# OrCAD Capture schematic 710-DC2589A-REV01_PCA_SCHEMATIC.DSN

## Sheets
1 PAGE1: size C; note: 100MHz Isolated DAC SPI Serial Interface Demo Circuit
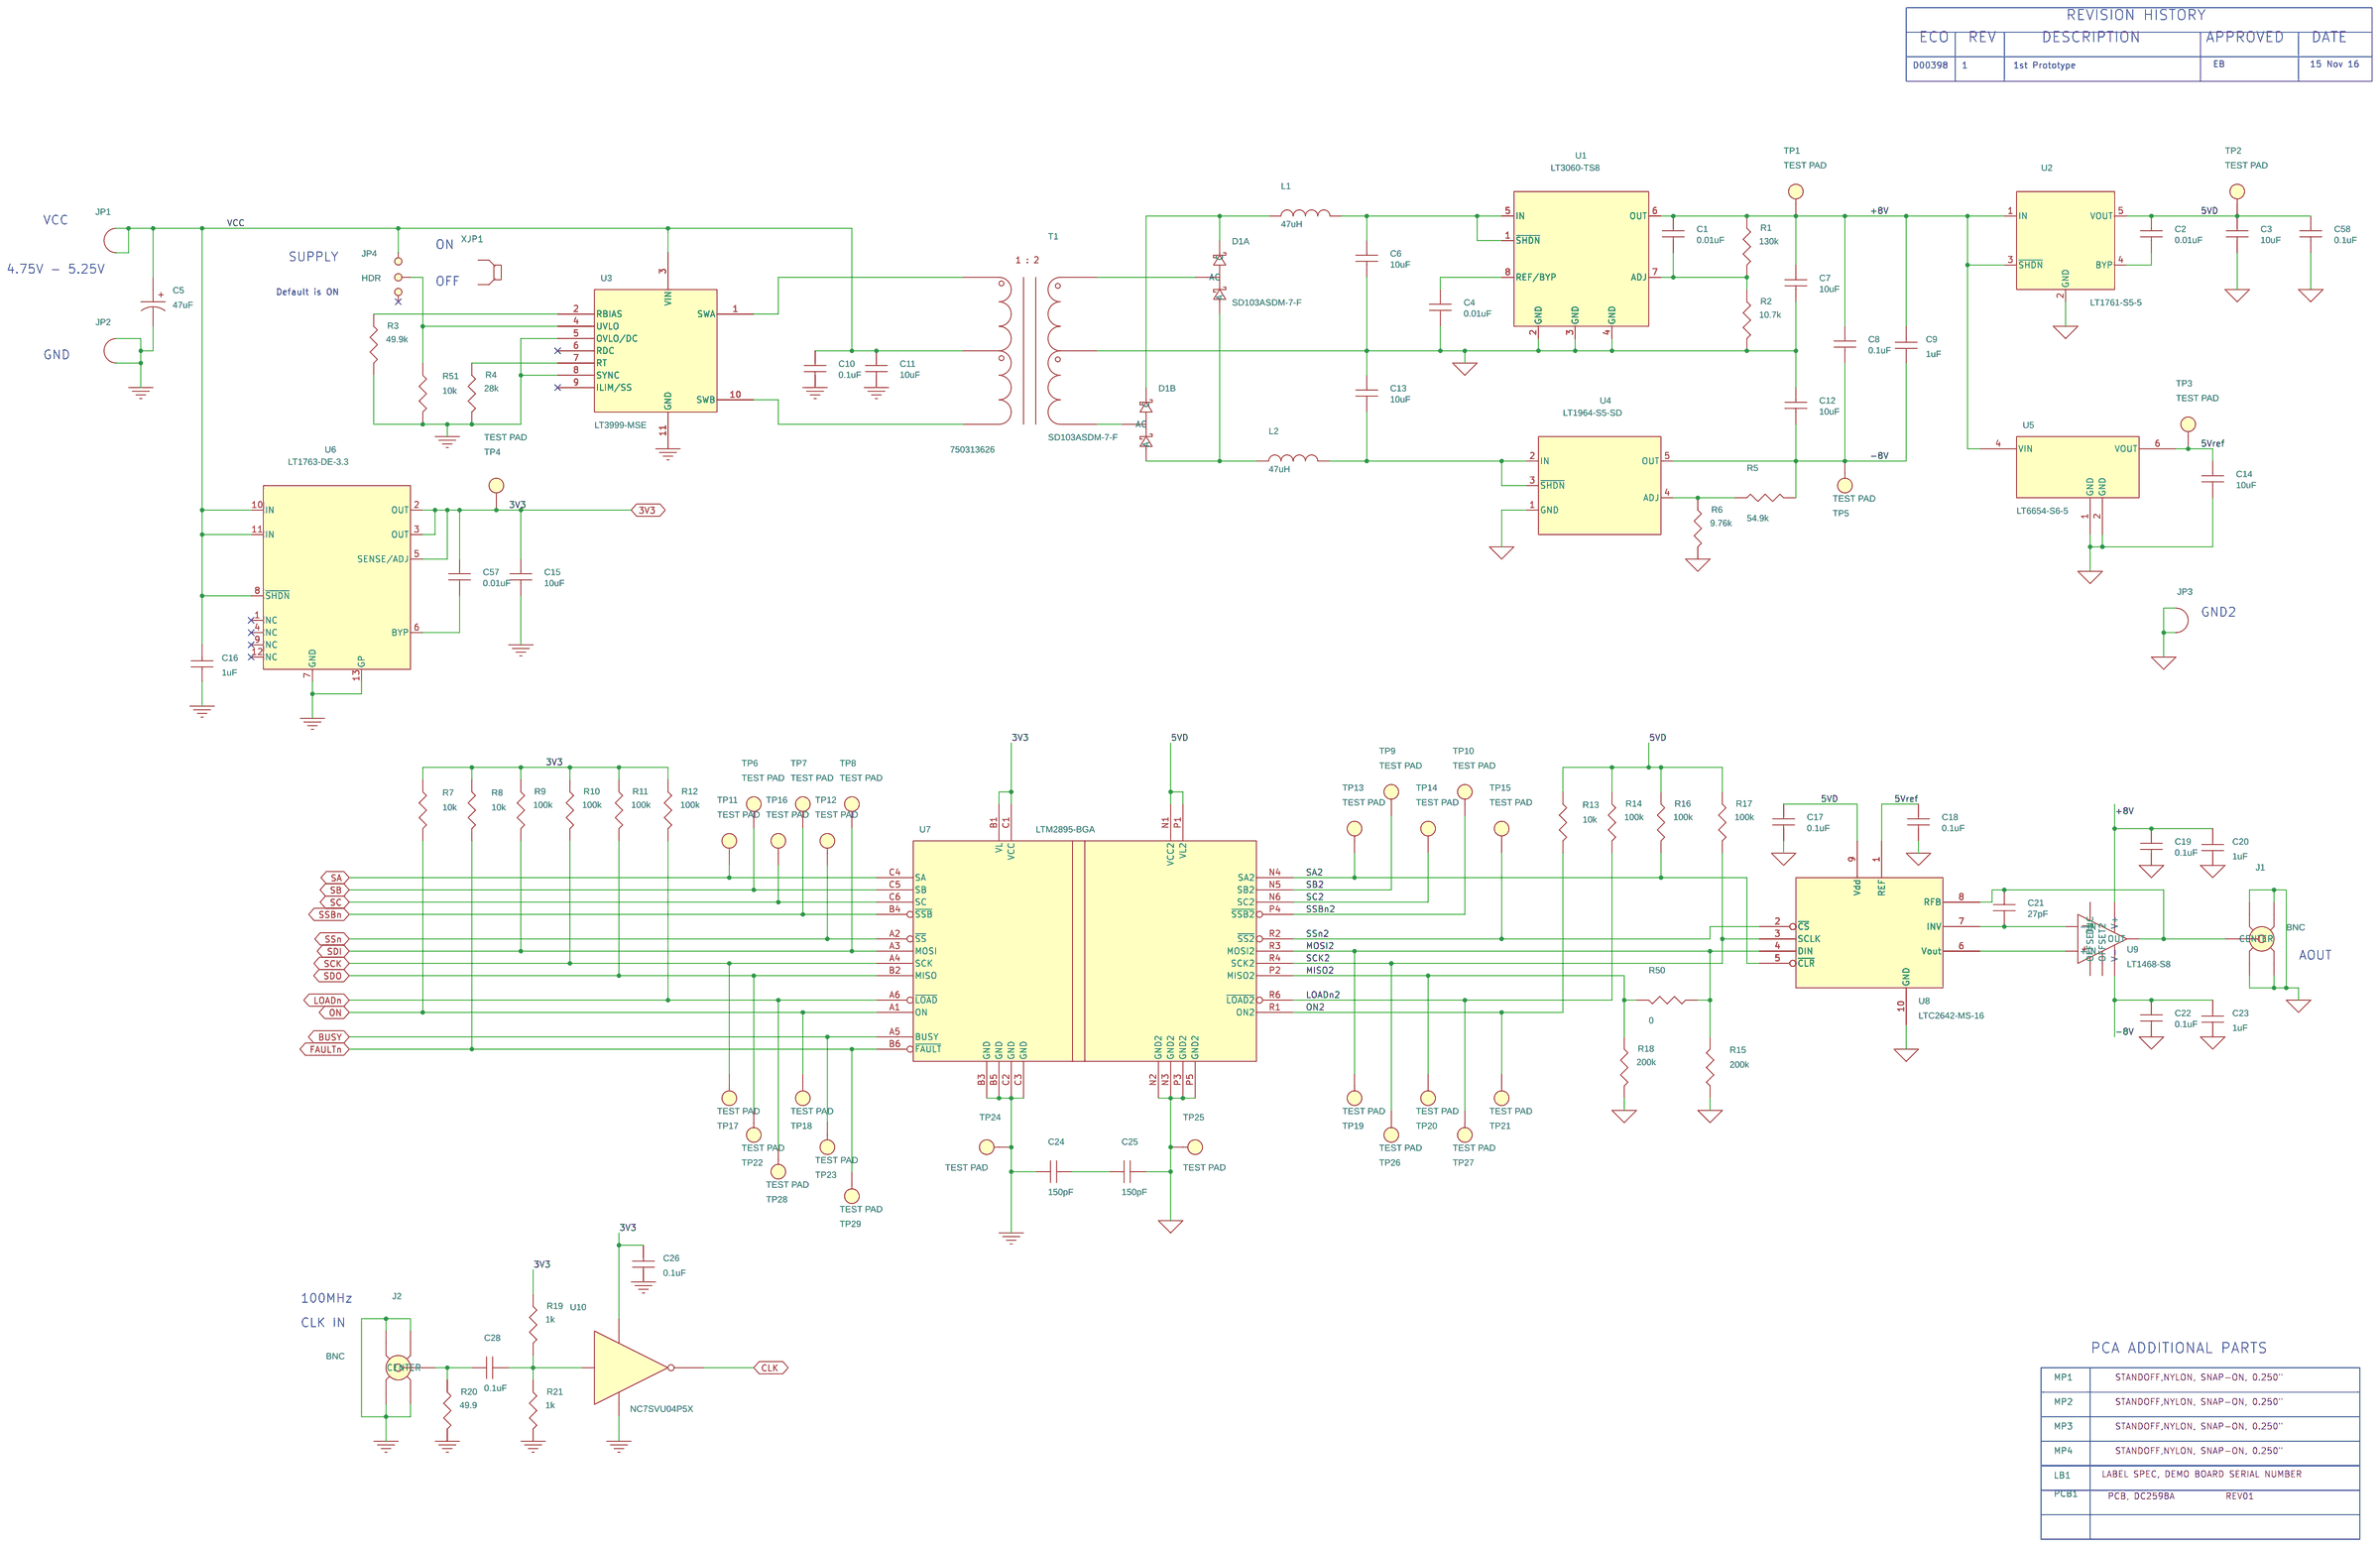
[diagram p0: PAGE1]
2 PAGE2: size C
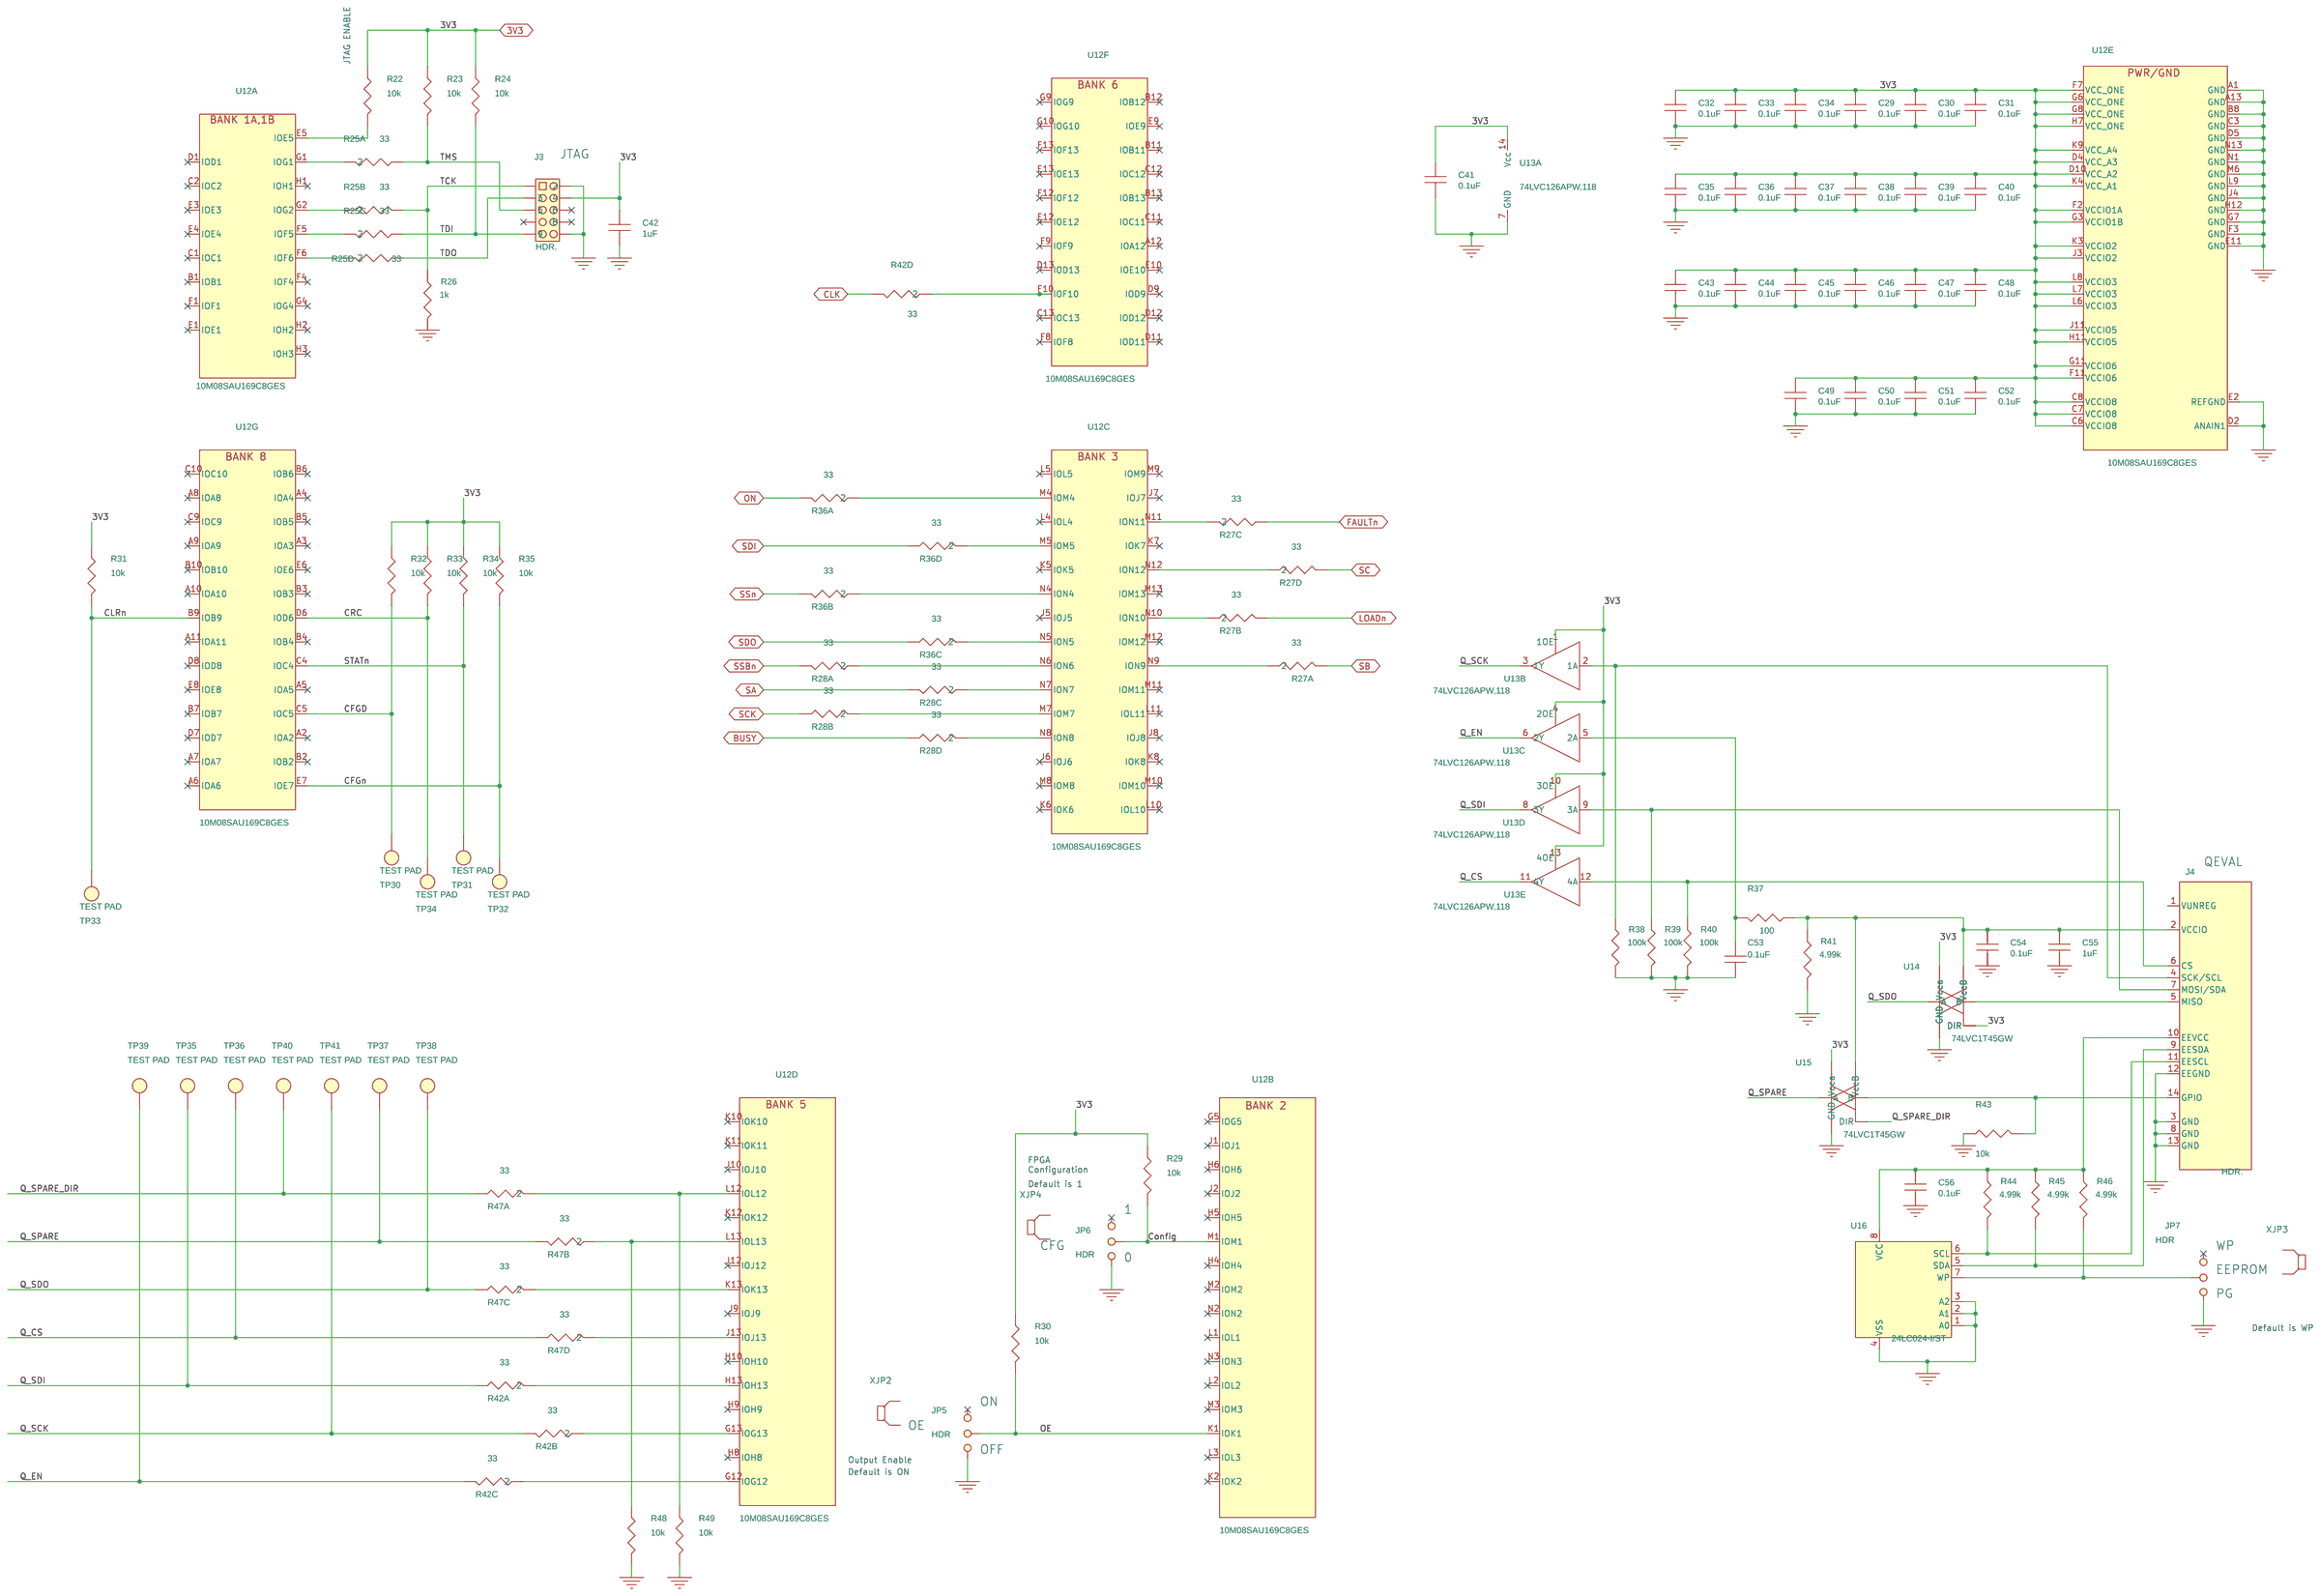
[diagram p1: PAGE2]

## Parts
sheet PAGE1
C1  0.01uF  [CC0402N]
C2  0.01uF  [CC0402N]
C3  10uF  [CC1210N]
C4  0.01uF  [CC0402N]
C5  47uF  [CAPMP6032N]
C6  10uF  [CC1210N]
C7  10uF  [CC1210N]
C8  0.1uF  [CC0402N]
C9  1uF  [CC0603N]
C10  0.1uF  [CC0402N]
C11  10uF  [CC1210N]
C12  10uF  [CC1210N]
C13  10uF  [CC1210N]
C14  10uF  [CC1210N]
C15  10uF  [CC1210N]
C16  1uF  [CC0603N]
C17  0.1uF  [CC0402N]
C18  0.1uF  [CC0402N]
C19  0.1uF  [CC0402N]
C20  1uF  [CC0603N]
C21  27pF  [CC0402N]
C22  0.1uF  [CC0402N]
C23  1uF  [CC0603N]
C24  150pF  [CC1808N]
C25  150pF  [CC1808N]
C26  0.1uF  [CC0402N]
C28  0.1uF  [CC0402N]
C57  0.01uF  [CC0402N]
C58  0.1uF  [CC0402N]
D1  SD103ASDM-7-F  [DIODES-SOT26-6]  (sections A,B)
J1  BNC  [AMPHENOL-112640]
J2  BNC  [AMPHENOL-112640]
JP1  HEAT SINK PASSIVE BGA ANCHOR  [AAVID_125700D00000G]
JP2  HEAT SINK PASSIVE BGA ANCHOR  [AAVID_125700D00000G]
JP3  HEAT SINK PASSIVE BGA ANCHOR  [AAVID_125700D00000G]
JP4  HDR  [HD1X3-079]
L1  47uH  [COILCRAFT-XFL3012]
L2  47uH  [COILCRAFT-XFL3012]
LB1  LABEL  [895-0154_REV01]
MP1  STANDOFF  [MTG-8831]
MP2  STANDOFF  [MTG-8831]
MP3  STANDOFF  [MTG-8831]
MP4  STANDOFF  [MTG-8831]
PCB1  PCB, DC2598A
R1  130k  [CR0402N]
R2  10.7k  [CR0603N]
R3  49.9k  [CR0603N]
R4  28k  [CR0603N]
R5  54.9k  [CR0603N]
R6  9.76k  [CR0402N]
R7  10k  [CR0402N]
R8  10k  [CR0402N]
R9  100k  [CR0603N]
R10  100k  [CR0603N]
R11  100k  [CR0603N]
R12  100k  [CR0603N]
R13  10k  [CR0402N]
R14  100k  [CR0603N]
R15  200k  [CR0603N]
R16  100k  [CR0603N]
R17  100k  [CR0603N]
R18  200k  [CR0603N]
R19  1k  [CR0603N]
R20  49.9  [CR1206N]
R21  1k  [CR0603N]
R50  0  [CR0805N]
R51  10k  [CR0402N]
T1  750313626  [WURTH-PKG-0948]
TP1  TEST PAD  [PADSTYLE1]
TP2  TEST PAD  [PADSTYLE1]
TP3  TEST PAD  [PADSTYLE1]
TP4  TEST PAD  [PADSTYLE1]
TP5  TEST PAD  [PADSTYLE1]
TP6  TEST PAD  [PADSTYLE1]
TP7  TEST PAD  [PADSTYLE1]
TP8  TEST PAD  [PADSTYLE1]
TP9  TEST PAD  [PADSTYLE1]
TP10  TEST PAD  [PADSTYLE1]
TP11  TEST PAD  [PADSTYLE1]
TP12  TEST PAD  [PADSTYLE1]
TP13  TEST PAD  [PADSTYLE1]
TP14  TEST PAD  [PADSTYLE1]
TP15  TEST PAD  [PADSTYLE1]
TP16  TEST PAD  [PADSTYLE1]
TP17  TEST PAD  [PADSTYLE1]
TP18  TEST PAD  [PADSTYLE1]
TP19  TEST PAD  [PADSTYLE1]
TP20  TEST PAD  [PADSTYLE1]
TP21  TEST PAD  [PADSTYLE1]
TP22  TEST PAD  [PADSTYLE1]
TP23  TEST PAD  [PADSTYLE1]
TP24  TEST PAD  [PADSTYLE1]
TP25  TEST PAD  [PADSTYLE1]
TP26  TEST PAD  [PADSTYLE1]
TP27  TEST PAD  [PADSTYLE1]
TP28  TEST PAD  [PADSTYLE1]
TP29  TEST PAD  [PADSTYLE1]
U1  LT3060-TS8  [LTC-TS8-8-1637]
U2  LT1761-S5-5  [LTC-S5-5-1635]
U3  LT3999-MSE  [LTC-MSE-10-1664]
U4  LT1964-S5-SD  [LTC-S5-5-1635]
U5  LT6654-S6-5  [LTC-S6-6-1636]
U6  LT1763-DE-3.3  [LTC-DE/UE-12-1695]
U7  LTM2895-BGA  [LTC-BGA-36-1987]
U8  LTC2642-MS-16  [LTC-MS-10-1661]
U9  LT1468-S8  [LTC-S8-8-1610(S8)]
U10  NC7SVU04P5X  [SC70-5]
XJP1  SHUNT
sheet PAGE2
C29  0.1uF  [CC0402N]
C30  0.1uF  [CC0402N]
C31  0.1uF  [CC0402N]
C32  0.1uF  [CC0402N]
C33  0.1uF  [CC0402N]
C34  0.1uF  [CC0402N]
C35  0.1uF  [CC0402N]
C36  0.1uF  [CC0402N]
C37  0.1uF  [CC0402N]
C38  0.1uF  [CC0402N]
C39  0.1uF  [CC0402N]
C40  0.1uF  [CC0402N]
C41  0.1uF  [CC0402N]
C42  1uF  [CC0805N]
C43  0.1uF  [CC0402N]
C44  0.1uF  [CC0402N]
C45  0.1uF  [CC0402N]
C46  0.1uF  [CC0402N]
C47  0.1uF  [CC0402N]
C48  0.1uF  [CC0402N]
C49  0.1uF  [CC0402N]
C50  0.1uF  [CC0402N]
C51  0.1uF  [CC0402N]
C52  0.1uF  [CC0402N]
C53  0.1uF  [CC0402N]
C54  0.1uF  [CC0402N]
C55  1uF  [CC0805N]
C56  0.1uF  [CC0402N]
J3  HDR.  [SAMTEC_TSW-105-07-L-D]
J4  HDR.  [HD2X7-079-MOLEX]
JP5  HDR  [HD1X3-079]
JP6  HDR  [HD1X3-079]
JP7  HDR  [HD1X3-079]
R22  10k  [CR0402N]
R23  10k  [CR0402N]
R24  10k  [CR0402N]
R25  33  [PANASONIC-EXB38V]  (sections A,B,C,D)
R26  1k  [CR0603N]
R27  33  [PANASONIC-EXB38V]  (sections A,B,C,D)
R28  33  [PANASONIC-EXB38V]  (sections A,B,C,D)
R29  10k  [CR0402N]
R30  10k  [CR0402N]
R31  10k  [CR0402N]
R32  10k  [CR0402N]
R33  10k  [CR0402N]
R34  10k  [CR0402N]
R35  10k  [CR0402N]
R36  33  [PANASONIC-EXB38V]  (sections A,B,C,D)
R37  100  [CR0603N]
R38  100k  [CR0603N]
R39  100k  [CR0603N]
R40  100k  [CR0603N]
R41  4.99k  [CR0603N]
R42  33  [PANASONIC-EXB38V]  (sections A,B,C,D)
R43  10k  [CR0402N]
R44  4.99k  [CR0603N]
R45  4.99k  [CR0603N]
R46  4.99k  [CR0603N]
R47  33  [PANASONIC-EXB38V]  (sections A,B,C,D)
R48  10k  [CR0402N]
R49  10k  [CR0402N]
TP30  TEST PAD  [PADSTYLE1]
TP31  TEST PAD  [PADSTYLE1]
TP32  TEST PAD  [PADSTYLE1]
TP33  TEST PAD  [PADSTYLE1]
TP34  TEST PAD  [PADSTYLE1]
TP35  TEST PAD  [PADSTYLE1]
TP36  TEST PAD  [PADSTYLE1]
TP37  TEST PAD  [PADSTYLE1]
TP38  TEST PAD  [PADSTYLE1]
TP39  TEST PAD  [PADSTYLE1]
TP40  TEST PAD  [PADSTYLE1]
TP41  TEST PAD  [PADSTYLE1]
U12  10M08SAU169C8GES  [ALTERA-169UBGA]  (sections A,B,C,D,E,F,G)
U13  74LVC126APW,118  [TSSOP-14N]  (sections A,B,C,D,E)
U14  74LVC1T45GW  [NXP-SOT363]
U15  74LVC1T45GW  [NXP-SOT363]
U16  24LC024-I/ST  [MICROCHIP-TSSOP-8]
XJP2  SHUNT
XJP3  SHUNT
XJP4  SHUNT

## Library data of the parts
C1 C2 C4 C57 = CAP: CAP.,0.01uF,X7R,50V,10%,0402; CLASS: DISCRETE; Dielectric Type: X7R; FPLIST: CC0402N,CC0402L,CC0402M; Manufacturer: KEMET; Manufacturer PN: C0402C103K5RAC7867; PART_NUMBER: 150-0041; Package Size: 0402; Rated Voltage: 50V; Tolerance: 10%
C3 C6 C7 C11-C15 = CAP: CAP.,10uF,X7R,35V,10%,1210; CLASS: DISCRETE; Dielectric Type: X7R; FPLIST: CC1210N,CC1210L,CC1210M; Manufacturer: MURATA; Manufacturer PN: GRM32ER7YA106KA12L; PART_NUMBER: 150-0365; Package Size: 1210; Rated Voltage: 35V; Tolerance: 10%
C5 = CAP_P: CAP.,47uF,16V,10%,2413; CLASS: DISCRETE; FPLIST: CAPMP6032N,CAPMP6032L,CAPMP6032M; Manufacturer: Kemet; Manufacturer PN: T494C476K016AT; PART_NUMBER: 150-0521; Package Size: 2413; Package Type: Surface Mount; Rated Voltage: 16V; Tolerance: 10%
C8 C10 C17-C19 C22 C26 C28-C41 C43-C54 C56 C58 = CAP: CAP.,0.1uF,X7R,50V,10%,0402; CLASS: DISCRETE; Dielectric Type: X7R; FPLIST: CC0402N,CC0402L,CC0402M; Manufacturer: MURATA; Manufacturer PN: GRM155R71H104KE14D; PART_NUMBER: 150-3240; Package Size: 0402; Package Type: SMD; Rated Voltage: 50V; Tolerance: 10%
C9 C16 C20 C23 = CAP: CAP.,1uF,X7R,35V,10%,0603; CLASS: DISCRETE; Dielectric Type: X7R; FPLIST: CC0603N,CC0603L,CC0603M; Manufacturer: TDK; Manufacturer PN: C1608X7R1V105K080AC; PART_NUMBER: 150-0522; Package Size: 0603; Package Type: Surface Mount, MLCC; Rated Voltage: 35V; Temperature Coefficient: X7R; Tolerance: 10%
C21 = CAP: CAP.,27pF,C0G,50V,5%,0402; CLASS: DISCRETE; Dielectric Type: C0G; FPLIST: CC0402N,CC0402L,CC0402M; Manufacturer: MURATA; Manufacturer PN: GRM1555C1H270JZ01D; PART_NUMBER: 150-0093; Package Size: 0402; Rated Voltage: 50V; Tolerance: 5%
C24 C25 = CAP: CAP CER 150PF 250VAC X7R 1808; CLASS: DISCRETE; Dielectric Type: X7R; FPLIST: CC1808N,CC1808L,CC1808M; Manufacturer: MURATA; Manufacturer PN: GA342QR7GF151KW01L; PART_NUMBER: 150-0523; Package Size: 1808; Package Type: Surface Mount, MLCC; Rated Voltage: 250VAC; Temperature Coefficient: X7R; Tolerance: 10%
D1 = DIODES-SD103ASDM: DIODE,SCHOTTKY,40V,225mW,SOT-26; CLASS: DISCRETE; Manufacturer: DIODES,INC; PART_NUMBER: 210-0233; Package Size: SOT-26-6; Rated Voltage: 40V
J1 J2 = BNC_50_OHM_112404: CONN.,BNC,FEMALE,16.97mm X 11.02mm,EDGE MT; CLASS: IO; Manufacturer: AMPHENOL; Manufacturer PN: 112640; Operating Temperature Minimum: -55C - 85C; PART_NUMBER: 250-0631
JP1-JP3 = test_probe_jumper: Heat Sink Passive BGA Anchor; CLASS: DISCRETE; Manufacturer: Aavid Thermalloy; Manufacturer PN: 125700D00000G; PART_NUMBER: 930-0004
JP4-JP7 = 3_PIN_HEADER_.079_SINGLE_ROW: CONN.,HDR,MALE,1x3,2mm,THT, STR; CLASS: IO; Manufacturer: Wurth Elektronik; Manufacturer PN: 62000311121; PART_NUMBER: 250-0484
L1 L2 = IND: IND.,47uH,POWER SHIELDED,20%,460mA,1212; CLASS: DISCRETE; Manufacturer: Coilcraft; Manufacturer PN: XFL3012-473MEB; PART_NUMBER: 200-0446; Package Size: 1212; Tolerance: 20%
LB1 = BLANK_LABEL: LABEL SPEC, DEMO BOARD SERIAL NUMBER; Manufacturer: BRADY; Manufacturer PN: THT-96-717-10; PART_NUMBER: 895-0154
MP1-MP4 = BLANK_MECHANICAL_PART: STANDOFF,NYLON, SNAP-ON, 0.250"; CLASS: MECHANICAL PART; Manufacturer: KEYSTONE; Manufacturer PN: 8831; PART_NUMBER: 763-0006
PCB1 = BLANK_PCB_PART: BOM Notes: REV01; CLASS: DISCRETE; Manufacturer: EAGLE ELECTRONICS, INC; Manufacturer PN: 600-DC2598A; PART_NUMBER: 600-DC2598A
R1 = RES: RES.,130k OHMS,1%,1/16W,0402; CLASS: DISCRETE; FPLIST: CR0402N,CR0402L,CR0402M; Manufacturer: NIC; Manufacturer PN: NRC04F1303TRF; PART_NUMBER: 100-2547; Package Size: 0402; Rated Power: 1/16W; Temperature Coefficient: 100ppm/C; Tolerance: 1%
R2 = RES: RES.,10.7k OHMS,1%,1/10W,0603; CLASS: DISCRETE; FPLIST: CR0603N,CR0603L,CR0603M; Manufacturer: NIC; Manufacturer PN: NRC06F1072TRF; PART_NUMBER: 100-2719; Package Size: 0603; Rated Power: 1/10W; Temperature Coefficient: 100ppm/C; Tolerance: 1%
R3 = RES: RES.,49.9k OHMS,1%,1/10W,0603; CLASS: DISCRETE; FPLIST: CR0603N,CR0603L,CR0603M; Manufacturer: VISHAY; Manufacturer PN: CRCW060349K9FKEA; PART_NUMBER: 100-0303; Package Size: 0603; Rated Power: 1/10W; Temperature Coefficient: 100ppm/C; Tolerance: 1%
R4 = RES: RES.,28k OHMS,1%,1/10W,0603; CLASS: DISCRETE; FPLIST: CR0603N,CR0603L,CR0603M; Manufacturer: PANASONIC; Manufacturer PN: ERJ3EKF2802V; PART_NUMBER: 100-0094; Package Size: 0603; Rated Power: 1/10W; Temperature Coefficient: 100ppm/C; Tolerance: 1%
R5 = RES: RES.,54.9k OHMS,1%,1/10W,0603; CLASS: DISCRETE; FPLIST: CR0603N,CR0603L,CR0603M; Manufacturer: VISHAY; Manufacturer PN: CRCW060354K9FKEA; PART_NUMBER: 100-0336; Package Size: 0603; Rated Power: 1/10W; Temperature Coefficient: 100ppm; Tolerance: 1%
R6 = RES: RES.,9.76k OHMS,1%,1/16W,0402; CLASS: DISCRETE; FPLIST: CR0402N,CR0402L,CR0402M; Manufacturer: VISHAY; Manufacturer PN: CRCW04029K76FKED; PART_NUMBER: 100-0488; Package Size: 0402; Rated Power: 1/16W; Temperature Coefficient: 100ppm; Tolerance: 1%
R7 R8 R13 R22-R24 R29-R35 R43 R48 R49 R51 = RES: RES.,10k OHMS,1%,1/16W,0402; CLASS: DISCRETE; FPLIST: CR0402N,CR0402L,CR0402M; Manufacturer: NIC; Manufacturer PN: NRC04F1002TRF; PART_NUMBER: 100-2545; Package Size: 0402; Rated Power: 1/16W; Temperature Coefficient: 100ppm/C; Tolerance: 1%
R9-R12 R14 R16 R17 R38-R40 = RES: RES.,AEC-Q200,100k OHMS,5%,1/10W,0603; CLASS: DISCRETE; FPLIST: CR0603N,CR0603L,CR0603M; Manufacturer: VISHAY; Manufacturer PN: CRCW0603100KJNEA; PART_NUMBER: 100-0312; Package Size: 0603; Rated Power: 1/10W; Temperature Coefficient: 200ppm/C; Tolerance: 5%
R15 R18 = RES: RES.,200k OHMS,1%,1/10W,0603; CLASS: DISCRETE; FPLIST: CR0603N,CR0603L,CR0603M; Manufacturer: VISHAY; Manufacturer PN: CRCW0603200KFKEA; PART_NUMBER: 100-2378; Package Size: 0603; Rated Power: 1/10W; Temperature Coefficient: 100ppm/C; Tolerance: 1%
R19 R21 R26 = RES: RES.,1k OHM,1%,1/10W,0603; CLASS: DISCRETE; FPLIST: CR0603N,CR0603L,CR0603M; Manufacturer: NIC; Manufacturer PN: NRC06F1001TRF; PART_NUMBER: 100-2422; Package Size: 0603; Rated Power: 1/10W; Temperature Coefficient: 100ppm; Tolerance: 1%
R20 = RES: RES.,49.9 OHMS,1%,1/4W,1206; CLASS: DISCRETE; FPLIST: CR1206N,CR1206L,CR1206M; Manufacturer: NIC; Manufacturer PN: NRC12F49R9TRF; PART_NUMBER: 100-2791; Package Size: 1206; Rated Power: 1/4W; Temperature Coefficient: 100ppm/C; Tolerance: 1%
R50 = RES: RES.,0 OHM,1/8W,0805; CLASS: DISCRETE; FPLIST: CR0805N,CR0805L,CR0805M; Manufacturer: VISHAY; Manufacturer PN: CRCW08050000Z0EA; PART_NUMBER: 100-0024; Package Size: 0805; Rated Power: 1/8W
T1 = 750313626: TRANSFORMER,SWITCHING,2:1,9.14mm X 12.7mm; CLASS: DISCRETE; Manufacturer: WURTH ELEKTRONIK; PART_NUMBER: 410-0081; Package Size: 9.14mm L x 8.00mm W; Turns Ratio: 2:1
TP1-TP41 = PAD_STYLE_C: TESTPOINT, PCB COPPER FEATURE; CLASS: IO; FPLIST: PADSTYLE1,PADSTYLE2,PADSTYLE3,PADSTYLE4,PADSTYLE5,PADSTYLE6,PADSTYLE7,PADSTYLE8; Manufacturer: N/A; Manufacturer PN: N/A; PART_NUMBER: PCBPADS-1
U1 = LT3060-TS8-X: IC,LDO LINEAR REGULATOR,TSOT23-8; CLASS: IC; Manufacturer: LINEAR TECHNOLOGY; Manufacturer PN: LT3060ETS8#PBF; PART_NUMBER: LT3060ETS8#PBF; Package Size: SOT-23; Package Type: TSOT23-8
U2 = LT1761-S5-X: IC,LOW NOISE, LDO MICROPOWER REG.,TSOT23-5,100mA, 5V; CLASS: IC; Manufacturer: LINEAR TECHNOLOGY; Manufacturer PN: LT1761ES5-5#PBF; PART_NUMBER: LT1761ES5-5#PBF; Package Size: TSOT-23; Package Type: TSOT23-5
U3 = LT3999-MSE: IC,DC CONTROLLER, PUSH-PULL,10-pin MSOP EP; CLASS: IC; Manufacturer: LINEAR TECHNOLOGY; Manufacturer PN: LT3999IMSE#PBF; PART_NUMBER: LT3999IMSE#PBF; Package Type: 10-pin MSOP EP; Supply Voltage: 36 V
U4 = LT1964-S5-SD: IC,LDO Neg. Micropower Regulator,SOT23-5,200mA, 5V; CLASS: IC; Manufacturer: LINEAR TECHNOLOGY; Manufacturer PN: LT1964ES5-SD#PBF; PART_NUMBER: LT1964ES5-SD#PBF; Package Size: SOT23-5; Package Type: SOT23-5
U5 = LT6654-S6-X: Precision Wide Supply High Output Drive Low Noise Reference, SOT-23; CLASS: IC; Manufacturer: LINEAR TECHNOLOGY; Manufacturer PN: LT6654BHS6-5#TRMPBF; PART_NUMBER: LT6654BHS6-5#TRMPBF; Package Type: 6-pin TSOT-23
U6 = LT1763-DE-X: IC,Low Noise LDO Micropower REG,DFN-12,500mA, 3.3V; CLASS: IC; Manufacturer: LINEAR TECHNOLOGY; Manufacturer PN: LT1763CDE-3.3#PBF; PART_NUMBER: LT1763CDE-3.3#PBF; Package Type: DFN-12
U7 = LTM2895-BGA: IC,100MHz Isolated DAC SPI Serial; CLASS: IC; Manufacturer: LINEAR TECHNOLOGY; Manufacturer PN: LTM2895IY#PBF; PART_NUMBER: LTM2895IY#PBF
U8 = LTC2642-MS-X: IC,16-14-12-Bit VOUT DACs,10-pin MSOP; CLASS: IC; Manufacturer: LINEAR TECHNOLOGY; Manufacturer PN: LTC2642AIMS-16#PBF; PART_NUMBER: LTC2642AIMS-16#PBF; Package Type: 10-pin MSOP
U9 = LT1468-S8_ALT1: IC,70MHz 22us 16Bit Accurate OA,SO-8; CLASS: IC; Manufacturer: LINEAR TECHNOLOGY; Manufacturer PN: LT1468CS8#PBF; PART_NUMBER: LT1468CS8#PBF; Package Size: S8; Package Type: SO-8
U10 = NC7SVU04P5X-SC70-5: IC,ULP-A UNBUFFERED INVERTER,SC70-5; CLASS: IC; Manufacturer: FAIRCHILD SEMI; PART_NUMBER: 280-0491
XJP1-XJP4 = SHUNT_2MM: CONN.,SHUNT,FEMALE,2 POS,2mm; CLASS: IO; Manufacturer: SAMTEC; Manufacturer PN: 2SN-BK-G; PART_NUMBER: 250-0419
C42 C55 = CAP: CAP.,1uF,X7R,10V,10%,0805; CLASS: DISCRETE; Dielectric Type: X7R; FPLIST: CC0805N,CC0805L,CC0805M; Manufacturer: MURATA; Manufacturer PN: GRM21BR71A105KA01L; PART_NUMBER: 150-0153; Package Size: 0805; Rated Voltage: 10V; Tolerance: 10%
J3 = CONN._JTAG_2X5_0.100: CONN.,HDR.,MALE,2x5,2.54mm,THT, STR,MATTE TIN ON TAIL; CLASS: IO; Manufacturer: SAMTEC; Manufacturer PN: TSW-105-07-L-D; PART_NUMBER: 250-0518
J4 = CONN_2X7_.079_MOLEX_RIBBON_A: CONN.,HDR.,MALE,2x7,2mm,THT, VERT,SHROUDED; CLASS: IO; Manufacturer: MOLEX; Manufacturer PN: 87831-1420; PART_NUMBER: 250-0403
R25 R27 R28 R36 R42 R47 = ARRAY_4_RES_SMT_ALT: RES.,ARRAY AEC-Q200,33 OHMS,5%,1/16W,1206; CLASS: DISCRETE; Manufacturer: PANASONIC; Manufacturer PN: EXB-38V330JV; PART_NUMBER: 103-0024; Package Size: 1206; Rated Power: 1/16W; Temperature Coefficient: +/-200PPM; Tolerance: 5%
R37 = RES: RES.,AEC-Q200,100 OHMS,1%,1/10W,0603; CLASS: DISCRETE; Manufacturer: PANASONIC; Manufacturer PN: ERJ3EKF1000V; PART_NUMBER: 100-2769; Package Size: 0603; Rated Power: 1/10W; Temperature Coefficient: 100ppm/C; Tolerance: 1%
R41 R44-R46 = RES: RES.,4.99k OHMS,1%,1/10W,0603; CLASS: DISCRETE; FPLIST: CR0603N,CR0603L,CR0603M; Manufacturer: PANASONIC; Manufacturer PN: ERJ3EKF4991V; PART_NUMBER: 100-0121; Package Size: 0603; Rated Power: 1/10W; Temperature Coefficient: 100ppm/C; Tolerance: 1%
U12 = 10M08SAU169C8GES: IC,FPGA, MAX 10, 8000 CELLS,169 PIN UFBGA; CLASS: IC; Manufacturer: ALTERA; Manufacturer PN: 10M08SAU169C8G; PART_NUMBER: 280-0550; Package Type: 169 PIN UFBGA
U13 = 74LVC126A: IC,BUFF DVR TRI-ST QUAD,14-pin TSSOP; CLASS: IC; FPLIST: TSSOP-14N,TSSOP-14L,TSSOP-14M; Manufacturer: NXP Semiconductors; PART_NUMBER: 280-0599; Package Size: 14-TSSOP (0.173", 4.40mm Width); Package Type: 14-pin TSSOP; Supply Voltage: 1.2 V - 3.6 V
U14 U15 = 74LVC1T45: IC,DUAL SUPPLY TRANSCEIVER,SOT363-6 (SC88),SMD,3-STATE OUTPUTS; CLASS: IC; Manufacturer: NXP SEMICONDUCTORS; Manufacturer PN: 74LVC1T45GW,125; PART_NUMBER: 280-8080; Package Type: SOT363-6 (SC88),SMD
U16 = 24LC024-I_ST_TSSOP-8: IC,EEPROM, I2C,TSSOP-8,2Kb (256 x 8), 400kHz; CLASS: IC; Manufacturer: MICROCHIP; PART_NUMBER: 280-0494; Package Size: TSSOP-8; Package Type: TSSOP-8

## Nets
3V3: C15.1 C26.2 C29.1 C30.1 C31.1 C32.1 C33.1 C34.1 C35.1 C36.1 C37.1 C38.1 C39.1 C40.1 C41.1 C42.1 C43.1 C44.1 C45.1 C46.1 C47.1 C48.1 C49.1 C50.1 C51.1 C52.1 C57.1 J3.4 R7.1 R8.1 R9.1 R10.1 R11.1 R12.1 R19.1 R22.1 R23.1 R24.1 R29.1 R30.1 R31.1 R32.1 R33.1 R34.1 R35.1 TP4.1 U6.2(OUT) U6.3(OUT) U6.5(SENSE/ADJ) U7.B1(VL) U7.C1(VCC) U10.5 U12.C6(VCCIO8) U12.C7(VCCIO8) U12.C8(VCCIO8) U12.D4(VCC_A3) U12.D10(VCC_A2) U12.F2(VCCIO1A) U12.F7(VCC_ONE) U12.F11(VCCIO6) U12.G3(VCCIO1B) U12.G6(VCC_ONE) U12.G8(VCC_ONE) U12.G11(VCCIO6) U12.H7(VCC_ONE) U12.H11(VCCIO5) U12.J3(VCCIO2) U12.J11(VCCIO5) U12.K3(VCCIO2) U12.K4(VCC_A1) U12.K9(VCC_A4) U12.L6(VCCIO3) U12.L7(VCCIO3) U12.L8(VCCIO3) U13.1(1OE) U13.4(2OE) U13.10(3OE) U13.13(4OE) U13.14(Vcc) U14.1(Vcca) U14.5(DIR) U15.1(Vcca)
5VD: C2.1 C3.1 C17.1 C58.1 R13.1 R14.1 R16.1 R17.1 TP2.1 U2.5(VOUT) U7.N1(VCC2) U7.P1(VL2) U8.9(Vdd)
5Vref: C14.1 C18.1 TP3.1 U5.6(VOUT) U8.1(REF)
+8V: C1.1 C7.1 C8.1 C9.2 C19.1 C20.2 R1.1 TP1.1 U1.6(OUT) U2.1(IN) U2.3(~{SHDN}) U5.4(VIN) U9.7(V+)
-8V: C8.2 C9.1 C12.2 C22.1 C23.2 R5.2 TP5.1 U4.5(OUT) U9.4(V-)
GND: C5.2 C10.2 C11.2 C15.2 C16.1 C24.1 C26.1 C29.2 C30.2 C31.2 C32.2 C33.2 C34.2 C35.2 C36.2 C37.2 C38.2 C39.2 C40.2 C41.2 C42.2 C43.2 C44.2 C45.2 C46.2 C47.2 C48.2 C49.2 C50.2 C51.2 C52.2 C53.2 C54.2 C55.2 C56.2 J2.2 J2.3 J2.4 J2.5 J3.2 J3.10 J4.3(GND) J4.8(GND) J4.12(EEGND) J4.13(GND) JP2.1 JP2.2 JP5.1 JP6.1 JP7.1 R3.2 R4.2 R20.2 R21.2 R26.2 R38.2 R39.2 R40.2 R41.2 R43.1 R48.2 R49.2 R51.2 TP24.1 U3.5(OVLO/DC) U3.8(SYNC) U3.11(GND) U6.7(GND) U6.13(GP) U7.B3(GND) U7.B5(GND) U7.C2(GND) U7.C3(GND) U10.3 U12.A1(GND) U12.A13(GND) U12.B8(GND) U12.C3(GND) U12.D2(ANAIN1) U12.D5(GND) U12.E2(REFGND) U12.E11(GND) U12.F3(GND) U12.G7(GND) U12.H12(GND) U12.J4(GND) U12.L9(GND) U12.M6(GND) U12.N1(GND) U12.N13(GND) U13.7(GND) U14.2(GND) U15.2(GND) U16.1(A0) U16.2(A1) U16.3(A2) U16.4(VSS)
GND_SIGNAL: C3.2 C4.2 C6.2 C7.2 C12.1 C13.1 C14.2 C17.2 C18.2 C19.2 C20.1 C22.2 C23.1 C25.2 C58.2 J1.2 J1.3 J1.4 J1.5 JP3.1 JP3.2 R2.2 R6.2 R15.1 R18.2 T1.5 TP25.1 U1.2(GND) U1.3(GND) U1.4(GND) U2.2(GND) U4.1(GND) U5.1(GND) U5.2(GND) U7.N2(GND2) U7.N3(GND2) U7.P3(GND2) U7.P5(GND2) U8.10(GND)
VCC: C5.1 C10.1 C11.1 C16.2 JP1.1 JP1.2 JP4.3 T1.2 U3.3(VIN) U6.8(~{SHDN}) U6.10(IN) U6.11(IN)
BUSY: R28.4 TP23.1 U7.A5(BUSY)
CFGD: R32.2 TP30.1 U12.C5(IOC5)
CFGn: R35.2 TP32.1 U12.E7(IOE7)
CLK: R42.4 U10.4
CLRn: R31.2 TP33.1 U12.B9(IOB9)
Config: JP6.2 R29.2 U12.M1(IOM1)
CRC: R33.2 TP34.1 U12.D6(IOD6)
FAULTn: R8.2 R27.3 TP29.1 U7.B6(~{FAULT})
LOADn: R12.2 R27.2 TP28.1 U7.A6(~{LOAD})
LOADn2: R14.2 TP27.1 U7.R6(~{LOAD2})
MISO2: R18.1 R50.2 TP20.1 U7.P2(MISO2)
MOSI2: R15.2 R50.1 TP19.1 U7.R3(MOSI2) U8.4(DIN)
OE: JP5.2 R30.2 U12.K1(IOK1)
ON: R7.2 R36.1 TP18.1 U7.A1(ON)
ON2: R13.2 TP21.1 U7.R1(ON2)
Q_CS: R47.4 TP36.1 U13.11(4Y)
Q_EN: R42.3 TP39.1 U13.6(2Y)
Q_SCK: R42.2 TP41.1 U13.3(1Y)
Q_SDI: R42.1 TP35.1 U13.8(3Y)
Q_SDO: R47.3 TP38.1 U14.3(A)
Q_SPARE: R47.2 TP37.1 U15.3(A)
Q_SPARE_DIR: R47.1 TP40.1 U15.5(DIR)
SA: R28.3 TP11.1 U7.C4(SA)
SA2: R16.2 TP13.1 U7.N4(SA2) U8.5(~{CLR})
SB: R27.1 TP6.1 U7.C5(SB)
SB2: TP9.1 U7.N5(SB2)
SC: R27.4 TP16.1 U7.C6(SC)
SC2: TP14.1 U7.N6(SC2)
SCK: R10.2 R28.2 TP17.1 U7.A4(SCK)
SCK2: R17.2 TP26.1 U7.R4(SCK2) U8.3(SCLK)
SDI: R9.2 R36.4 TP8.1 U7.A3(MOSI)
SDO: R11.2 R36.3 TP22.1 U7.B2(MISO)
SSBn: R28.1 TP7.1 U7.B4(~{SSB})
SSBn2: TP10.1 U7.P4(~{SSB2})
SSn: R36.2 TP12.1 U7.A2(~{SS})
SSn2: TP15.1 U7.R2(~{SS2}) U8.2(~{CS})
STATn: R34.2 TP31.1 U12.C4(IOC4)
TCK: J3.1 R25.2 R26.1
TDI: J3.9 R24.2 R25.3
TDO: J3.3 R25.4
TMS: J3.5 R23.2 R25.1
N839686: U8.6(Vout) U9.3(+IN)
N839690: C21.2 U8.7(INV) U9.2(-IN)
N839694: C21.1 J1.1(CENTER) U8.8(RFB) U9.6(OUT)
N842809: D1.6(AC) T1.6
N842934: D1.2(C) D1.5(C) L1.1
N842958: D1.1(A) D1.4(A) L2.1
N843358: D1.3(AC) T1.4
N843663: T1.3 U3.10(SWB)
N843678: T1.1 U3.1(SWA)
N844267: C13.2 L2.2 U4.2(IN) U4.3(~{SHDN})
N844386: C6.1 L1.2 U1.1(~{SHDN}) U1.5(IN)
N844896: C4.1 U1.8(REF/BYP)
N844903: C1.2 R1.2 R2.1 U1.7(ADJ)
N848408: C2.2 U2.4(BYP)
N850776: R3.1 U3.2(RBIAS)
N850991: R4.1 U3.7(RT)
N864411: C24.2 C25.1
N864851: C56.1 J4.10(EEVCC) R44.1 R45.1 R46.1 U16.8(VCC)
N865521: J4.11(EESCL) R44.2 U16.6(SCL)
N865527: J4.4(SCK/SCL) R38.1 U13.2(1A)
N865545: J4.9(EESDA) R45.2 U16.5(SDA)
N865574: JP7.2 R46.2 U16.7(WP)
N866616: J4.5(MISO) U14.4(B)
N866898: C54.1 C55.1 J4.2(VCCIO) R37.1 R41.1 U14.6(VccB) U15.6(VccB)
N867394: J4.14(GPIO) R43.2 U15.4(B)
N870820: C53.1 R37.2 U13.5(2A)
N871031: J4.7(MOSI/SDA) R39.1 U13.9(3A)
N871063: J4.6(CS) R40.1 U13.12(4A)
N884294: R22.2 U12.E5(IOE5)
N886821: R25.5(2) U12.F6(IOF6)
N886823: R25.8(2) U12.G1(IOG1)
N886825: R25.6(2) U12.F5(IOF5)
N886827: R25.7(2) U12.G2(IOG2)
N901209: C28.1 J2.1(CENTER) R20.1
N901259: C28.2 R19.2 R21.1 U10.2
N1011225: R5.1 R6.1 U4.4(ADJ)
N1070687: R28.7(2) U12.M7(IOM7)
N1070714: R28.8(2) U12.N6(ION6)
N1072398: R27.5(2) U12.N12(ION12)
N1072420: R27.6(2) U12.N11(ION11)
N1072434: R27.7(2) U12.N10(ION10)
N1072455: R27.8(2) U12.N9(ION9)
N1072477: R28.5(2) U12.N8(ION8)
N1072491: R28.6(2) U12.N7(ION7)
N1072563: R36.5(2) U12.M5(IOM5)
N1072583: R36.6(2) U12.N5(ION5)
N1073332: R42.6(2) U12.G12(IOG12)
N1073362: R42.7(2) U12.G13(IOG13)
N1073406: R42.8(2) U12.H13(IOH13)
N1073498: R47.5(2) U12.J13(IOJ13)
N1073530: R47.6(2) U12.K13(IOK13)
N1074394: R42.5(2) U12.F10(IOF10)
N1083251: R36.7(2) U12.N4(ION4)
N1084028: R36.8(2) U12.M4(IOM4)
N1100302: JP4.2 R51.1 U3.4(UVLO)
N1100973: R47.8(2) R49.1 U12.L12(IOL12)
N1100977: R47.7(2) R48.1 U12.L13(IOL13)
N1101856: C57.2 U6.6(BYP)

Not connected (* = marked no-connect by the designer): J3 6* 7* 8*; J4 1(VUNREG); JP4 1*; JP5 3*; JP6 3*; JP7 3*; U3 6(RDC)* 9(ILIM/SS)*; U6 1(NC)* 4(NC)* 9(NC)* 12(NC)*; U9 1(OFFSET1) 5(OFFSET2) 8(DNC); U12 A2(IOA2)* A3(IOA3)* A4(IOA4)* A5(IOA5)* A6(IOA6)* A7(IOA7)* A8(IOA8)* A9(IOA9)* A10(IOA10)* A11(IOA11)* A12(IOA12)* B1(IOB1)* B2(IOB2)* B3(IOB3)* B4(IOB4)* B5(IOB5)* B6(IOB6)* B7(IOB7)* B10(IOB10)* B11(IOB11)* B12(IOB12)* B13(IOB13)* C1(IOC1)* C2(IOC2)* C9(IOC9)* C10(IOC10)* C11(IOC11)* C12(IOC12)* C13(IOC13)* D1(IOD1)* D7(IOD7)* D8(IOD8)* D9(IOD9)* D11(IOD11)* D12(IOD12)* D13(IOD13)* E1(IOE1)* E3(IOE3)* E4(IOE4)* E6(IOE6)* E8(IOE8)* E9(IOE9)* E10(IOE10)* E12(IOE12)* E13(IOE13)* F1(IOF1)* F4(IOF4)* F8(IOF8)* F9(IOF9)* F12(IOF12)* F13(IOF13)* G4(IOG4)* G5(IOG5)* G9(IOG9)* G10(IOG10)* H1(IOH1)* H2(IOH2)* H3(IOH3)* H4(IOH4)* H5(IOH5)* H6(IOH6)* H8(IOH8)* H9(IOH9)* H10(IOH10)* J1(IOJ1)* J2(IOJ2)* J5(IOJ5)* J6(IOJ6)* J7(IOJ7)* J8(IOJ8)* J9(IOJ9)* J10(IOJ10)* J12(IOJ12)* K2(IOK2)* K5(IOK5)* K6(IOK6)* K7(IOK7)* K8(IOK8)* K10(IOK10)* K11(IOK11)* K12(IOK12)* L1(IOL1)* L2(IOL2)* L3(IOL3)* L4(IOL4)* L5(IOL5)* L10(IOL10)* L11(IOL11)* M2(IOM2)* M3(IOM3)* M8(IOM8)* M9(IOM9)* M10(IOM10)* M11(IOM11)* M12(IOM12)* M13(IOM13)* N2(ION2)* N3(ION3)*

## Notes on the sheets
sheet 1
- REVISION HISTORY
- ECO
- REV
- DESCRIPTION
- APPROVED
- DATE
- D00398
- 1
- 1st Prototype
- EB
- 15 Nov 16
- VCC
- ON
- SUPPLY
- 4.75V - 5.25V
- OFF
- Default is ON
- GND
- GND2
- AOUT
- 100MHz
- CLK IN
- PCA ADDITIONAL PARTS
sheet 2
- JTAG ENABLE
- JTAG
- QEVAL
- FPGA
  Configuration
- Default is 1
- 1
- CFG
- WP
- 0
- EEPROM
- PG
- Default is WP
- ON
- OE
- OFF
- Output Enable
- Default is ON
